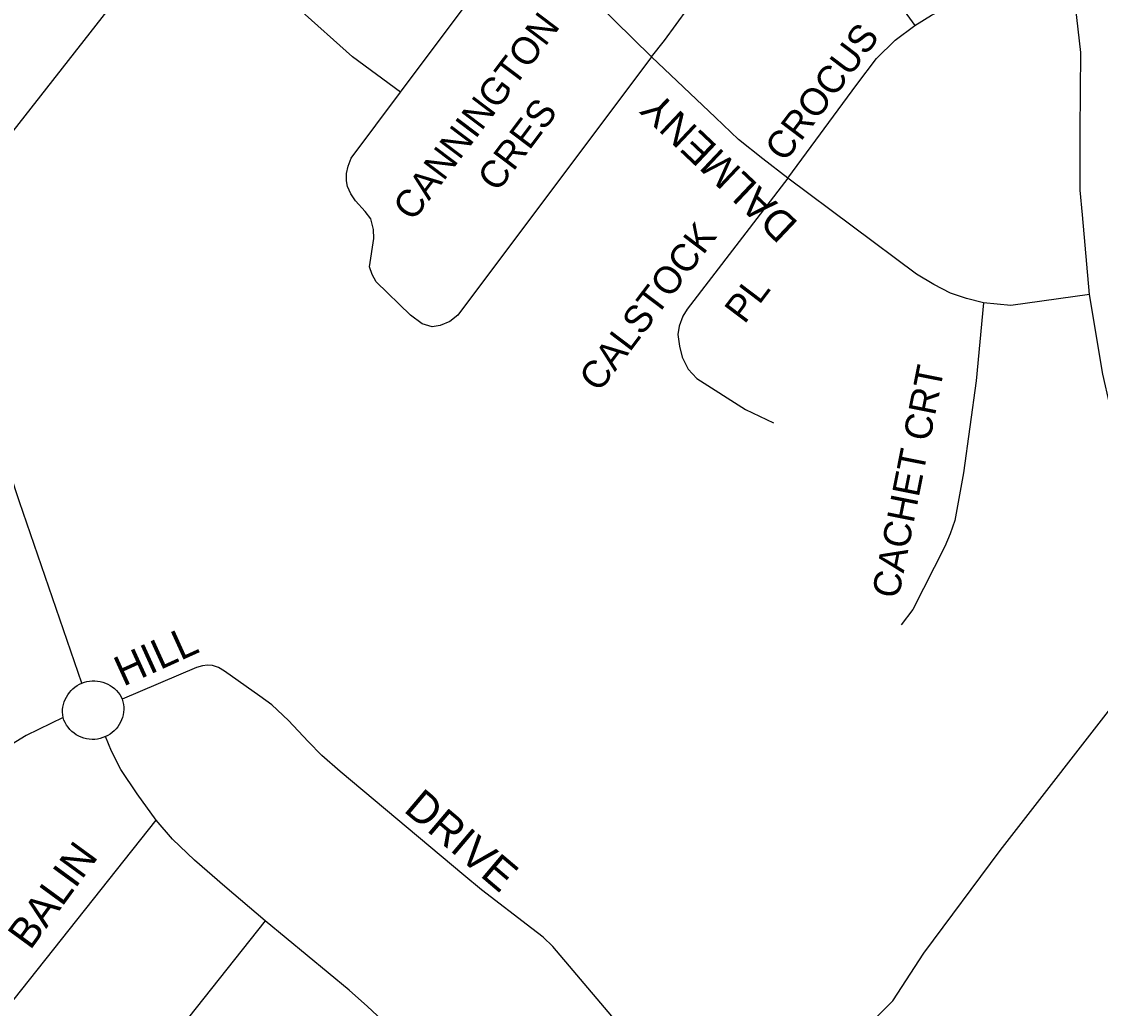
# Model space of a CAD drawing. Extents: x 586326 to 623965, y 4819854 to 4857850.
# Drawn here: x 595922 to 596463, y 4834124 to 4834619 of the extents above; entities that cross this region are included whole.
import ezdxf

# ---------------------------------------------------------------- set-up
doc = ezdxf.new("R2010")
doc.units = 0
for name, color, linetype in [('Lots_Concessions', 7, 'Continuous'), ('Minor Rd Lbls', 7, 'Continuous'), ('Minor Rds', 7, 'Continuous'), ('Proposed Secondary Rds', 7, 'Continuous')]:
    doc.layers.add(name, color=color, linetype=linetype)

msp = doc.modelspace()

# ---------------------------------------------------------------- linework, layer by layer
at = {"layer": 'Lots_Concessions'}
for p, q in [((595682.84, 4834264.23), (595978.21, 4834640.52)), ((596412.8, 4834203.47), (596495.86, 4834310.54)), ((596374.57, 4834152.11), (596412.8, 4834203.47)), ((596359.04, 4834128.13), (596374.57, 4834152.11)), ((596340.35, 4834109.68), (596359.04, 4834128.13))]:
    msp.add_line(p, q, dxfattribs=at)
at = {"layer": 'Minor Rds'}
for points in [[(596112.34, 4834583.51), (596088.2, 4834601.2), (596061.34, 4834625.23), (596058.18, 4834630.58), (596057.82, 4834635.98), (596060.4, 4834642.03), (596064.05, 4834646.29), (596115.45, 4834714.28)], [(596244.55, 4834609.43), (596297.12, 4834681.74), (596300.37, 4834684.32), (596303.94, 4834685.75), (596306.68, 4834685.95), (596310.34, 4834685.09), (596314.65, 4834682.66), (596331.62, 4834668.81), (596335.68, 4834664.11), (596370, 4834616.98)], [(596112.34, 4834583.51), (596173.18, 4834665.09)], [(596238.07, 4834601.13), (596173.18, 4834665.09)], [(596370, 4834616.98), (596378.4, 4834622.11), (596390.17, 4834627.94), (596403.56, 4834633.68), (596418.06, 4834637.73), (596433.27, 4834640.96), (596448.62, 4834643)], [(596306.35, 4834540.39), (596340.91, 4834587.35), (596350.83, 4834600.38), (596360.15, 4834609.56), (596370, 4834616.98)], [(596238.07, 4834601.13), (596244.55, 4834609.43)], [(596238.07, 4834601.13), (596141.05, 4834471.78), (596137.05, 4834468.62), (596132.24, 4834466.59), (596128.2, 4834466), (596123.16, 4834467.39), (596117.32, 4834471.84), (596100.14, 4834488.44), (596098.07, 4834492.1), (596096.83, 4834495.95), (596098.91, 4834510.15), (596098.73, 4834514.71), (596097.41, 4834519.99), (596094.59, 4834523.7), (596089.82, 4834528.99), (596087.37, 4834532.61), (596085.67, 4834536.31), (596085.24, 4834539.03), (596085.26, 4834542.76), (596086.14, 4834546.49), (596087.66, 4834550.4), (596112.34, 4834583.51)], [(596270.12, 4834570.87), (596238.07, 4834601.13)], [(596306.35, 4834540.39), (596293.9, 4834550.12), (596281.63, 4834559.71), (596270.12, 4834570.87)], [(596306.35, 4834540.39), (596255.89, 4834474.73), (596253.74, 4834471.26), (596251.95, 4834466.21), (596251.31, 4834462.1), (596252.04, 4834456.21), (596253.37, 4834450.67), (596256.45, 4834444.74), (596260.71, 4834439.96), (596285.1, 4834424.54), (596299.16, 4834417.87)], [(596404.41, 4834477.97), (596395.94, 4834480.14), (596387.88, 4834482.85), (596379.48, 4834487.13), (596370.89, 4834492.26), (596306.35, 4834540.39)], [(596457.53, 4834482.05), (596418.14, 4834476.61)], [(596404.41, 4834477.97), (596400.65, 4834438.92)], [(596418.14, 4834476.61), (596404.41, 4834477.97)], [(596400.65, 4834438.92), (596394.34, 4834392.84), (596389.96, 4834368.85), (596387.73, 4834362.19), (596385.01, 4834355.93), (596368.97, 4834324.3), (596363.22, 4834316.6)], [(596183.85, 4834160.12), (596178.05, 4834164.42), (596152.88, 4834183.75), (596144.04, 4834191.11), (596082.08, 4834243.14), (596072.96, 4834251.17), (596066.02, 4834258.06), (596056.15, 4834268.6), (596047.82, 4834276.47), (596041.82, 4834280.81), (596024.2, 4834293.45), (596021.06, 4834295.27), (596018.03, 4834296.24), (596015.66, 4834296.32), (596013.17, 4834296.07), (596010.03, 4834295.16), (595972.93, 4834279.31)], [(595943.22, 4834270.15), (595924.83, 4834261.09), (595917.38, 4834256.63), (595912.74, 4834252.53), (595907.49, 4834246.36), (595811.11, 4834124.39)], [(596044.5, 4834168.34), (595952.95, 4834052.9), (595949.43, 4834049.44), (595945.59, 4834047.92), (595942.21, 4834047.33), (595938.2, 4834047.7), (595934.97, 4834048.69), (595931.24, 4834050.99), (595897.11, 4834085.21), (595895.22, 4834088.9), (595894.65, 4834092.75), (595894.8, 4834096.21), (595896.43, 4834100.05), (595898.63, 4834103.95), (595989.93, 4834218.69)], [(596318.38, 4834008.59), (596302.24, 4834022.66), (596294.87, 4834030.49), (596283.86, 4834043.02), (596188.68, 4834155.44), (596183.85, 4834160.12)]]:
    msp.add_lwpolyline(points, dxfattribs=at)
at = {"layer": 'Proposed Secondary Rds'}
for points in [[(596453.92, 4834522.04), (596452.8, 4834534.43), (596452.79, 4834563.92), (596453.16, 4834603.38), (596448.62, 4834643)], [(596457.53, 4834482.05), (596453.92, 4834522.04)], [(596487.68, 4834369.62), (596479.48, 4834393.36), (596472.76, 4834411.01), (596467.77, 4834426.86), (596464.24, 4834442.24), (596457.53, 4834482.05)], [(595952.65, 4834287.34), (595921.44, 4834378.31), (595916.69, 4834392.41), (595906.93, 4834435.88)], [(595943.22, 4834270.15), (595943.05, 4834271.46), (595942.98, 4834272.78), (595943.03, 4834274.11), (595943.19, 4834275.42), (595943.46, 4834276.72), (595943.84, 4834277.99), (595944.33, 4834279.22), (595944.91, 4834280.41), (595945.6, 4834281.54), (595946.38, 4834282.61), (595947.24, 4834283.61), (595948.19, 4834284.54), (595949.21, 4834285.38), (595950.3, 4834286.13), (595951.45, 4834286.79), (595952.65, 4834287.34)], [(595952.65, 4834287.34), (595953.91, 4834287.8), (595955.21, 4834288.15), (595956.52, 4834288.39), (595957.86, 4834288.51), (595959.2, 4834288.53), (595960.53, 4834288.42), (595961.85, 4834288.2), (595963.15, 4834287.87), (595964.42, 4834287.43), (595965.64, 4834286.89), (595966.81, 4834286.24), (595967.92, 4834285.49), (595968.97, 4834284.65), (595969.94, 4834283.73), (595970.82, 4834282.72), (595971.62, 4834281.64), (595972.32, 4834280.5), (595972.93, 4834279.31)], [(595972.93, 4834279.31), (595973.26, 4834278.03), (595973.49, 4834276.73), (595973.6, 4834275.42), (595973.6, 4834274.1), (595973.49, 4834272.79), (595973.28, 4834271.49), (595972.95, 4834270.21), (595972.51, 4834268.97), (595971.97, 4834267.77), (595971.33, 4834266.61), (595970.6, 4834265.52), (595969.77, 4834264.49), (595968.86, 4834263.54), (595967.87, 4834262.66), (595966.82, 4834261.88), (595965.7, 4834261.18), (595964.52, 4834260.58)], [(595964.52, 4834260.58), (595963.23, 4834260.06), (595961.9, 4834259.66), (595960.54, 4834259.38), (595959.16, 4834259.22), (595957.77, 4834259.19), (595956.38, 4834259.28), (595955.01, 4834259.49), (595953.66, 4834259.82), (595952.35, 4834260.28), (595951.08, 4834260.85), (595949.87, 4834261.53), (595948.72, 4834262.31), (595947.65, 4834263.2), (595946.66, 4834264.17), (595945.76, 4834265.24), (595944.97, 4834266.37), (595944.27, 4834267.58), (595943.69, 4834268.84), (595943.22, 4834270.15)], [(595989.93, 4834218.69), (595980.32, 4834231.85), (595972.19, 4834244.05), (595967.51, 4834253.34), (595964.52, 4834260.58)], [(596044.5, 4834168.34), (596024.22, 4834185.55), (596009.12, 4834198.71), (595998.07, 4834209.21), (595989.93, 4834218.69)], [(596103.12, 4834118.44), (596095.77, 4834125.38), (596086.53, 4834133.62), (596044.5, 4834168.34)]]:
    msp.add_lwpolyline(points, dxfattribs=at)

# ---------------------------------------------------------------- texts
at = {"layer": 'Minor Rd Lbls'}
for s, height, rotation, p in [('CANNINGTON', 13.691, 52.9473, (596118.53, 4834518.27)), ('CROCUS', 13.691, 52.8741, (596304.82, 4834547.9)), ('CRES', 13.691, 52.9473, (596160.85, 4834532.92)), ('DALMENY', 15.009, 136.5998, (596312.15, 4834517.89)), ('CALSTOCK', 13.691, 52.8741, (596211.74, 4834432.63)), ('PL', 13.691, 52.8741, (596284.64, 4834466.88)), ('CACHET CRT', 13.691, 78.7373, (596361.79, 4834329.26)), ('HILL', 15.116, 24.4223, (595973.43, 4834285.54)), ('DRIVE', 15.726, 319.7461, (596113.35, 4834223.4)), ('BALIN', 15.116, 53.8462, (595926.78, 4834153.22))]:
    msp.add_text(s, height=height, rotation=rotation, dxfattribs=at).set_placement(p)

doc.saveas('drawing.dxf')
